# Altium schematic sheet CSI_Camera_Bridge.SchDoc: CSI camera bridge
size A3; Project: STM32MP15x-EVAL; Date: Not used; ApprovedBy: Not used; CheckedBy: Not used; Author: Not used; CompanyName: STMicroelectronics; DrawnBy: Not used; Engineer: Not used; Organization: Not used; Address1: Not used; Address2: Not used; Address3: Not used; Address4: Not used; DocumentNumber: 11; Revision: Not used; SheetNumber: 11; SheetTotal: 17
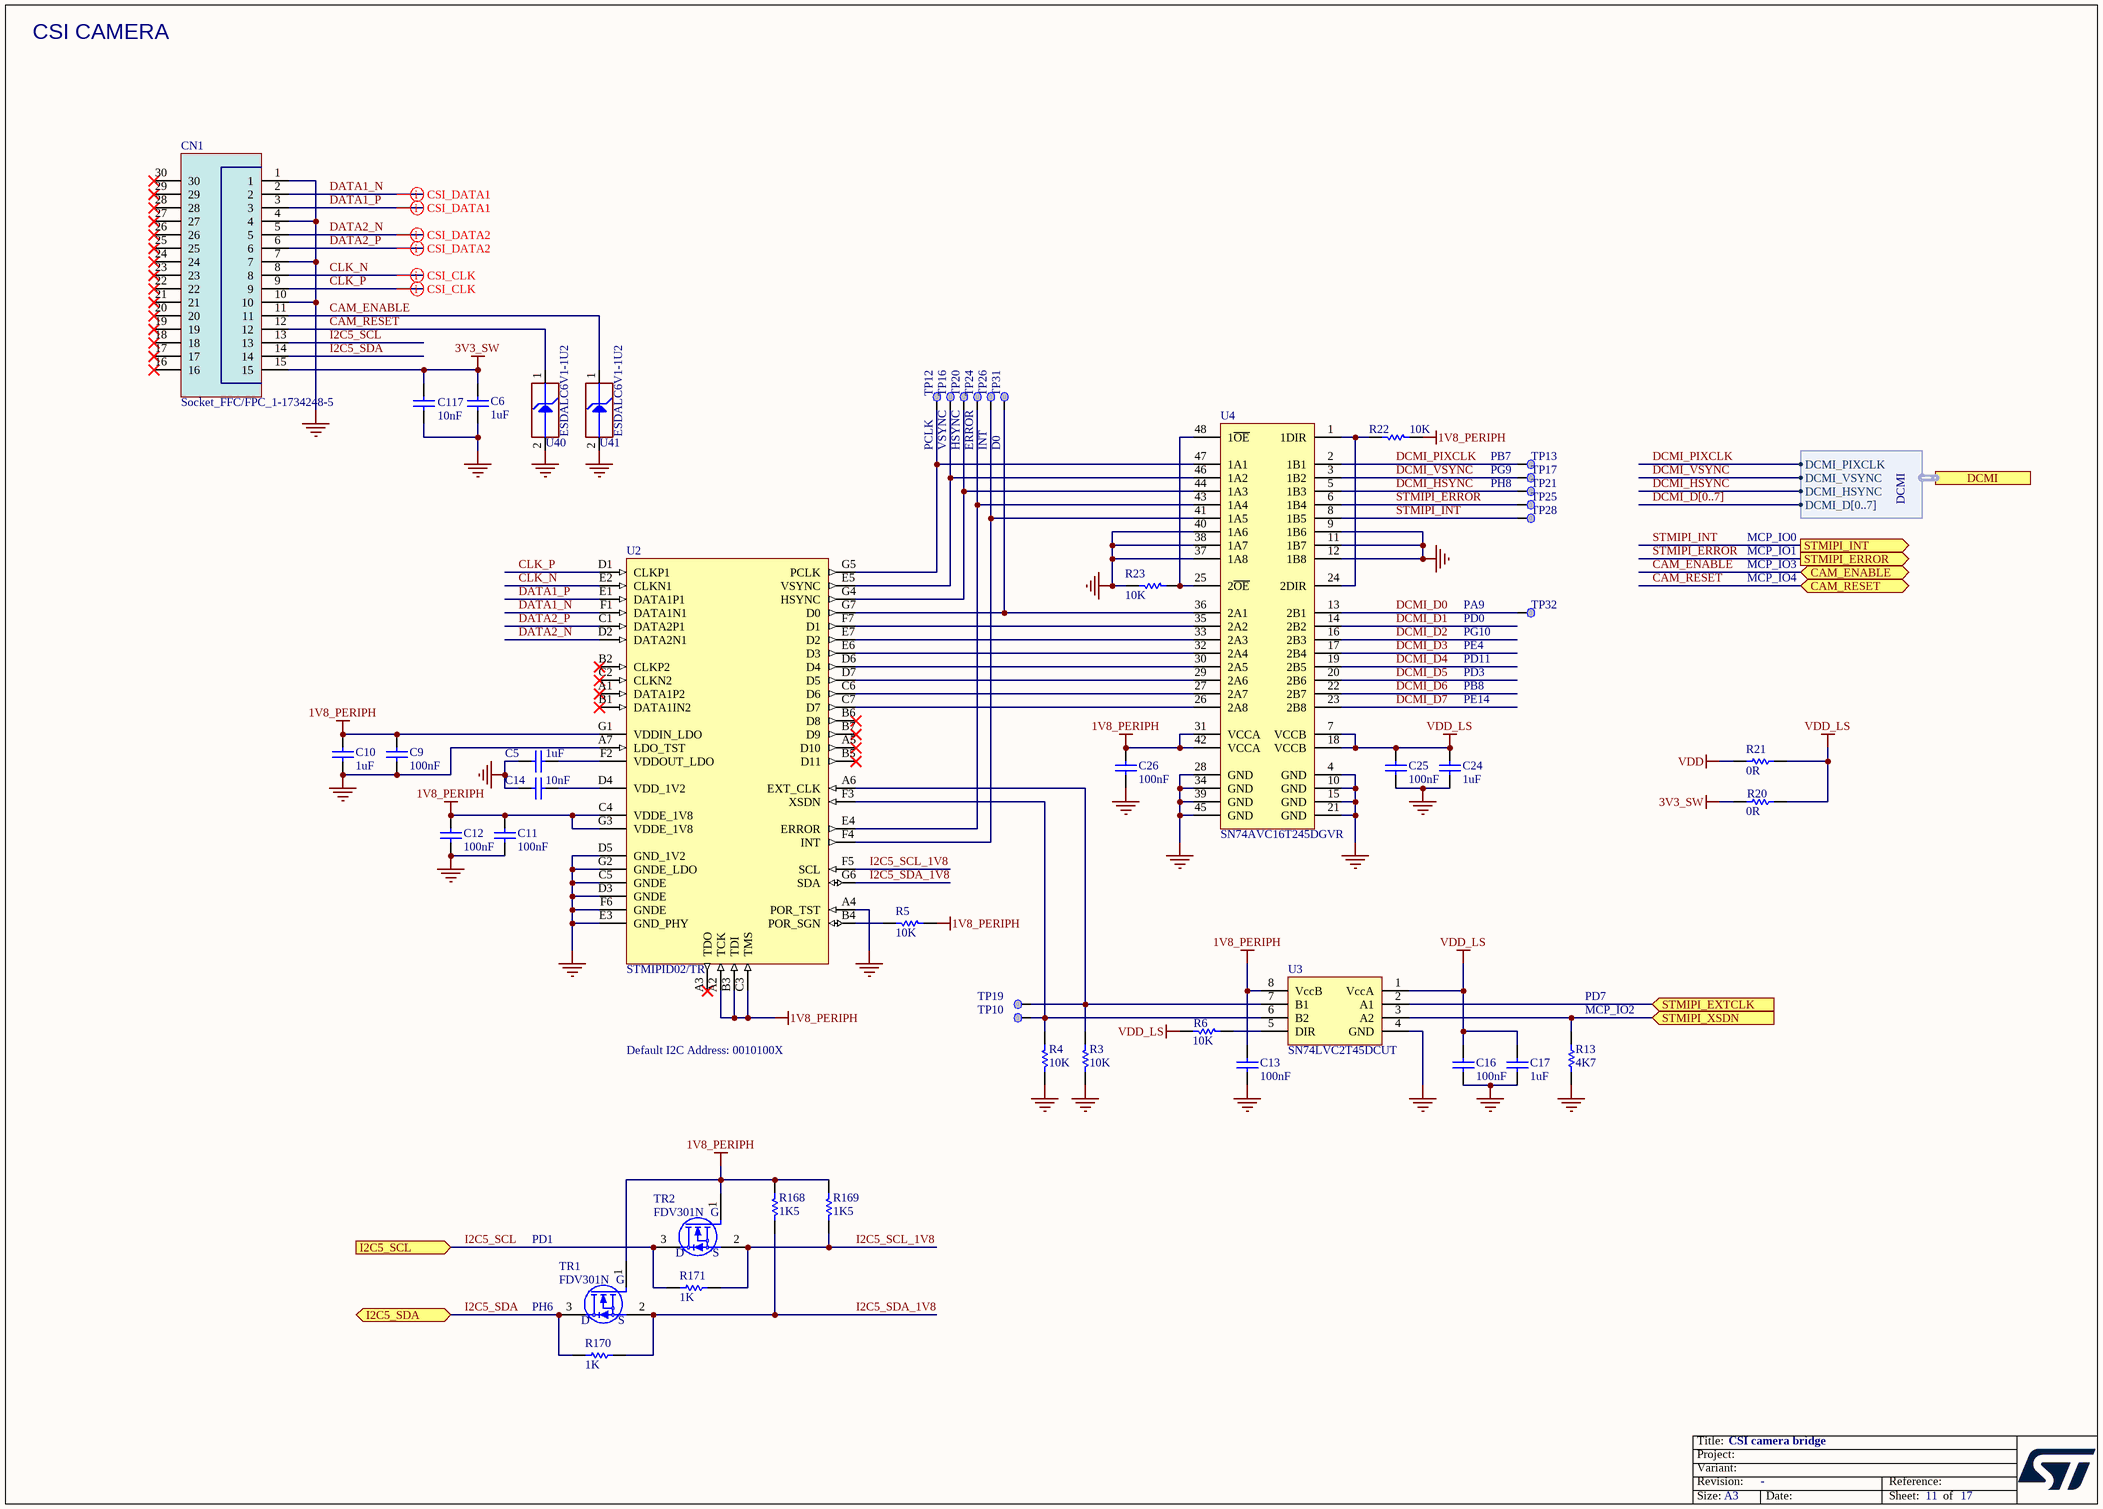
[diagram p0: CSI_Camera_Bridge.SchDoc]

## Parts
C5  value 1uF  [C0201_MURATA_GRM033_H0P3]  (hidden comment: Capacitor)
C6  value 1uF  [C0402]  (hidden comment: Capacitor)
C9  value 100nF  [C0402]  (hidden comment: Capacitor)
C10  value 1uF  [C0201_MURATA_GRM033_H0P3]  (hidden comment: Capacitor)
C11  value 100nF  [C0402]  (hidden comment: Capacitor)
C12  value 100nF  [C0402]  (hidden comment: Capacitor)
C13  value 100nF  [C0402]  (hidden comment: Capacitor)
C14  value 10nF  [C0402]  (hidden comment: Capacitor)
C16  value 100nF  [C0402]  (hidden comment: Capacitor)
C17  value 1uF  [C0201_MURATA_GRM033_H0P3]  (hidden comment: Capacitor)
C24  value 1uF  [C0201_MURATA_GRM033_H0P3]  (hidden comment: Capacitor)
C25  value 100nF  [C0402]  (hidden comment: Capacitor)
C26  value 100nF  [C0402]  (hidden comment: Capacitor)
C117  value 10nF  [C0402]  (hidden comment: Capacitor)
CN1  Socket_FFC/FPC_1-1734248-5  [CON_TE-CONNECTIVITY_1-1734248-5]
R3  value 10K  [R0402]  (hidden comment: Resistor)
R4  value 10K  [R0402]  (hidden comment: Resistor)
R5  value 10K  [R0402]  (hidden comment: Resistor)
R6  value 10K  [R0402]  (hidden comment: Resistor)
R13  value 4K7  [R0402]  (hidden comment: Resistor)
R20  value 0R  [R0402]  (hidden comment: Resistor)
R21  value 0R  [R0402]  (hidden comment: Resistor)
R22  value 10K  [R0402]  (hidden comment: Resistor)
R23  value 10K  [R0402]  (hidden comment: Resistor)
R168  value 1K5  [R0402]  (hidden comment: Resistor)
R169  value 1K5  [R0402]  (hidden comment: Resistor)
R170  value 1K  [R0402]  (hidden comment: Resistor)
R171  value 1K  [R0402]  (hidden comment: Resistor)
TP10  Test Point  [TP_SMD_1MM]  (value not drawn)  (no BOM)
TP12  Test Point  [TP_SMD_1MM]  (value not drawn)  (no BOM)
TP13  Test Point  [TP_SMD_1MM]  (value not drawn)  (no BOM)
TP16  Test Point  [TP_SMD_1MM]  (value not drawn)  (no BOM)
TP17  Test Point  [TP_SMD_1MM]  (value not drawn)  (no BOM)
TP19  Test Point  [TP_SMD_1MM]  (value not drawn)  (no BOM)
TP20  Test Point  [TP_SMD_1MM]  (value not drawn)  (no BOM)
TP21  Test Point  [TP_SMD_1MM]  (value not drawn)  (no BOM)
TP24  Test Point  [TP_SMD_1MM]  (value not drawn)  (no BOM)
TP25  Test Point  [TP_SMD_1MM]  (value not drawn)  (no BOM)
TP26  Test Point  [TP_SMD_1MM]  (value not drawn)  (no BOM)
TP28  Test Point  [TP_SMD_1MM]  (value not drawn)  (no BOM)
TP31  Test Point  [TP_SMD_1MM]  (value not drawn)  (no BOM)
TP32  Test Point  [TP_SMD_1MM]  (value not drawn)  (no BOM)
TR1  value FDV301N  [MOS_SOT23]  (hidden comment: BSN20)
TR2  value FDV301N  [MOS_SOT23]  (hidden comment: BSN20)
U2  value STMIPID02/TR  [ICC_VFBGA49_3X3_P040]  (hidden comment: STMIPID02)
U3  SN74LVC2T45DCUT  [ICC_VSSOP8_DCU_R-PDSO-G8_2X2P30_P050]
U4  SN74AVC16T245DGVR  [ICC_TVSOP48_9P8X6P6_P040]
U40  value ESDALC6V1-1U2  [ESD_ST0201]  (hidden comment: ESD-TRANSIL)
U41  value ESDALC6V1-1U2  [ESD_ST0201]  (hidden comment: ESD-TRANSIL)

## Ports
CAM_ENABLE (bidir), CAM_RESET (bidir), DCMI (harness DCMI), I2C5_SCL (in), I2C5_SDA (bidir), STMIPI_ERROR (out), STMIPI_EXTCLK (in), STMIPI_INT (out), STMIPI_XSDN (in)

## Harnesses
DCMI: DCMI_D[0..7], DCMI_HSYNC, DCMI_VSYNC, DCMI_PIXCLK

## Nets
1V8_PERIPH: C9.2 C10.2 C11.2 C12.2 C13.2 C26.2 R5.1 R22.2 R168.2 R169.2 TR1.1(G) TR2.1(G) U2.A2(TCK) U2.B3(TDI) U2.C3(TMS) U2.C4(VDDE_1V8) U2.G1(VDDIN_LDO) U2.G3(VDDE_1V8) U3.8(VccB) U4.31(VCCA) U4.42(VCCA)
3V3_SW: C6.2 C117.2 CN1.15 R20.2
GND: C5.1 C6.1 C9.1 C10.1 C11.1 C12.1 C13.1 C14.1 C16.1 C17.1 C24.1 C25.1 C26.1 C117.1 CN1.1 CN1.4 CN1.7 CN1.10 R3.2 R4.2 R13.1 R23.2 U2.A4(POR_TST) U2.A7(LDO_TST) U2.C5(GNDE) U2.D3(GNDE) U2.D5(GND_1V2) U2.E3(GND_PHY) U2.F6(GNDE) U2.G2(GNDE_LDO) U3.4(GND) U4.4(GND) U4.9(1B6) U4.10(GND) U4.11(1B7) U4.12(1B8) U4.15(GND) U4.21(GND) U4.28(GND) U4.34(GND) U4.37(1A8) U4.38(1A7) U4.39(GND) U4.40(1A6) U4.45(GND) U40.2(GND) U41.2(GND)
VDD: R21.2
VDD_LS: C16.2 C17.2 C24.2 C25.2 R6.2 R20.1 R21.1 U3.1(VccA) U4.7(VCCB) U4.18(VCCB)
CAM_ENABLE: CN1.11 U41.1(IO1) ; port CAM_ENABLE
CAM_RESET: CN1.12 U40.1(IO1) ; port CAM_RESET
CLK_N: CN1.8 U2.E2(CLKN1)
CLK_P: CN1.9 U2.D1(CLKP1)
DATA1_N: CN1.2 U2.F1(DATA1N1)
DATA1_P: CN1.3 U2.E1(DATA1P1)
DATA2_N: CN1.5 U2.D2(DATA2N1)
DATA2_P: CN1.6 U2.C1(DATA2P1)
DCMI_D0: TP32.1 U4.13(2B1)
DCMI_D1: U4.14(2B2)
DCMI_D2: U4.16(2B3)
DCMI_D3: U4.17(2B4)
DCMI_D4: U4.19(2B5)
DCMI_D5: U4.20(2B6)
DCMI_D6: U4.22(2B7)
DCMI_D7: U4.23(2B8)
DCMI_HSYNC: TP21.1 U4.5(1B3) ; port DCMI.DCMI_HSYNC
DCMI_PIXCLK: TP13.1 U4.2(1B1) ; port DCMI.DCMI_PIXCLK
DCMI_VSYNC: TP17.1 U4.3(1B2) ; port DCMI.DCMI_VSYNC
I2C5_SCL: CN1.13 R171.2 TR2.3(D) ; port I2C5_SCL
I2C5_SCL_1V8: R169.1 R171.1 TR2.2(S) U2.F5(SCL)
I2C5_SDA: CN1.14 R170.2 TR1.3(D) ; port I2C5_SDA
I2C5_SDA_1V8: R168.1 R170.1 TR1.2(S) U2.G6(SDA)
STMIPI_ERROR: TP25.1 U4.6(1B4) ; port STMIPI_ERROR
STMIPI_EXTCLK: U3.2(A1) ; port STMIPI_EXTCLK
STMIPI_INT: TP28.1 U4.8(1B5) ; port STMIPI_INT
STMIPI_XSDN: R13.2 U3.3(A2) ; port STMIPI_XSDN
NetC5_2: C5.2 U2.F2(VDDOUT_LDO)
NetC14_2: C14.2 U2.D4(VDD_1V2)
NetR3_1: R3.1 TP19.1 U2.A6(EXT_CLK) U3.7(B1)
NetR4_1: R4.1 TP10.1 U2.F3(XSDN) U3.6(B2)
NetR5_2: R5.2 U2.B4(POR_SGN)
NetR6_1: R6.1 U3.5(DIR)
NetR22_1: R22.1 U4.1(1DIR) U4.24(2DIR)
NetR23_1: R23.1 U4.25(2~{OE}) U4.48(1~{OE})
NetTP12_1: TP12.1 U2.G5(PCLK) U4.47(1A1)
NetTP16_1: TP16.1 U2.E5(VSYNC) U4.46(1A2)
NetTP20_1: TP20.1 U2.G4(HSYNC) U4.44(1A3)
NetTP24_1: TP24.1 U2.E4(ERROR) U4.43(1A4)
NetTP26_1: TP26.1 U2.F4(INT) U4.41(1A5)
NetTP31_1: TP31.1 U2.G7(D0) U4.36(2A1)
NetU2_C6: U2.C6(D6) U4.27(2A7)
NetU2_C7: U2.C7(D7) U4.26(2A8)
NetU2_D6: U2.D6(D4) U4.30(2A5)
NetU2_D7: U2.D7(D5) U4.29(2A6)
NetU2_E6: U2.E6(D3) U4.32(2A4)
NetU2_E7: U2.E7(D2) U4.33(2A3)
NetU2_F7: U2.F7(D1) U4.35(2A2)

Not connected (* = marked no-connect by the designer): CN1 16* 17* 18* 19* 20* 21* 22* 23* 24* 25* 26* 27* 28* 29* 30*; U2 A1(DATA1P2)* A3(TDO)* A5(D10)* B1(DATA1IN2)* B2(CLKP2)* B5(D11)* B6(D8)* B7(D9)* C2(CLKN2)*

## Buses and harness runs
bus DCMI_D[0..7]

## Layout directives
differential pair: CLK_N, CLK_P, DATA1_N, DATA1_P, DATA2_N, DATA2_P

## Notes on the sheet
- CSI CAMERA
- PCLK
- VSYNC
- HSYNC
- ERROR
- INT
- D0
- PH8
- PG9
- PB7
- MCP_IO1
- MCP_IO0
- MCP_IO4
- MCP_IO3
- (near TP32) PA9
- (near TP32) PD0
- (near TP32) PG10
- PE4
- PD11
- PD3
- PB8
- PE14
- Default I2C Address: 0010100X
- (near R13) PD7
- (near R13) MCP_IO2
- PD1
- PH6

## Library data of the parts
C5 C10 C17 C24 = MCD-02377: Capacitor, MLCC, 1uF, 6.3V, X5R, +/-20%, 0201, T=0,3mm; Manufacturer_Part_Number: GRM033R60J105MEA2; Manufacturer: MURATA; Part_Preference: Recommended; Partial_Alternate_Internal_Part_Number: MCD-04356; Order_Code_RS: 820-0643; Component_Country_Of_Origin: Japan°; ShowFields: YES; ID: 4483
C6 = MCD-00095: Capacitor, MLCC, 1uF, 25V, X5R, +/-10%, 0402, T=0.5mm; Manufacturer_Part_Number: GRM155R61E105KA12; Manufacturer: MURATA; Part_Preference: Recommended; Partial_Alternate_Internal_Part_Number: MCD-04188; Order_Code_RS: 2218855; Component_Country_Of_Origin: Japan°°; ShowFields: YES; ID: 2772
C9 C11-C13 C16 C25 C26 = MCD-00006: Capacitor, MLCC, 100nF, 16V, X7R, +/-10%, 0402, T=0.5mm; Manufacturer_Part_Number: CC0402KRX7R7BB104; Manufacturer: YAGEO; Part_Preference: Recommended; Partial_Alternate_Internal_Part_Number: MCD-03299; Order_Code_RS: 9402047; Component_Country_Of_Origin: China; ShowFields: YES; ID: 2474
C14 = MCD-02198: Capacitor, MLCC, 10nF, 50V, X7R, +/-10%, 0402, T=0.5mm; Manufacturer_Part_Number: CC0402KRX7R9BB103; Manufacturer: YAGEO; Part_Preference: Recommended; Order_Code_RS: 6169644; Component_Country_Of_Origin: China; ShowFields: YES; ID: 4298
C117 = MCD-02198: Capacitor, MLCC, 10nF, 50V, X7R, +/-10%, 0402, T=0.5mm; Part_Preference: Recommended; Manufacturer: YAGEO; Manufacturer_Part_Number: CC0402KRX7R9BB103; Order_Code_RS: 6169644; Component_Country_Of_Origin: China; ShowFields: YES; ID: 4298
CN1 = MCD-02225: Socket_FFC/FPC, 15pins, 1mm ,VR, SMD, T=7.7mm; Part_Preference: Recommended; Part_Type: Connector; Manufacturer: TE CONNECTIVITY; Component_Country_Of_Origin: Taiwan; ShowFields: YES; ID: 4325
R3 R4 R6 R22 R23 = MCD-00053: Resistor, 10K, 0402, +/-1%, 1/16W; Part_Preference: Recommended; Manufacturer: YAGEO; Manufacturer_Part_Number: RC0402FR-0710KL; BMS_Part_Number: 9131590; Order_Code_RS: 9239359; Component_Country_Of_Origin: China; ShowFields: YES; ID: 2539
R5 = MCD-00053: Resistor, 10K, 0402, +/-1%, 1/16W; BMS_Part_Number: 9131590; Part_Preference: Recommended; Manufacturer: YAGEO; Manufacturer_Part_Number: RC0402FR-0710KL; Order_Code_RS: 9239359; Component_Country_Of_Origin: China; ShowFields: YES; ID: 2539
R13 = MCD-00065: Resistor, 4K7, 0402, +/-1%, 1/16W; Manufacturer_Part_Number: RC0402FR-074K7L; Manufacturer: YAGEO; Part_Preference: Recommended; Partial_Alternate_Internal_Part_Number: MCD-03300; Order_Code_RS: 9239316; Component_Country_Of_Origin: China; ShowFields: YES; ID: 2526
R20 R21 = MCD-00052: Resistor, 0R, 0402, +/-5%, 1/16W; Part_Preference: Recommended; Manufacturer: YAGEO; Manufacturer_Part_Number: RC0402JR-070RL; Order_Code_RS: 9232516RL; Component_Country_Of_Origin: China; ShowFields: YES; ID: 2540
R168 R169 = MCD-00068: Resistor, 1K5, 0402, +/-1%, 1/16W; Part_Preference: Recommended; Manufacturer: YAGEO; Manufacturer_Part_Number: RC0402FR-071K5L; Order_Code_RS: 9239251; Component_Country_Of_Origin: China; ShowFields: YES; ID: 2524
R170 R171 = MCD-00061: Resistor, 1K, 0402, +/-1%,1/16W; Part_Preference: Recommended; Manufacturer: YAGEO; Manufacturer_Part_Number: RC0402FR-071KL; Order_Code_RS: 9239235; Component_Country_Of_Origin: China; ShowFields: YES; ID: 2532
TP10 TP12 TP13 TP16 TP17 TP19-TP21 TP24-TP26 TP28 TP31 TP32 = MCD-00074: Test Point 1mm; Part_Type: Misc; Part_Preference: Recommended; ShowFields: YES; ID: 2518; Component_Country_Of_Origin: Unknown
TR1 TR2 = MCD-02156: MOSFET, N-Channel , Vds: 25V, Id: 0,22A, Vgs(th): 1.06V, Vgs(max): +/-8V, Rdson:5ohm@Vgs=2.7V, Qg=0,49nC; Part_Preference: Recommended; Part_Type: Transistor; Manufacturer: ON SEMICONDUCTOR; Component_Country_Of_Origin: China°°; ShowFields: YES; ID: 4256
U2 = MCD-02213: Dual mode MIPI CSI-2 / SMIA CCP2 de-serializer; Part_Preference: Forbidden; Part_Type: IC; Manufacturer: STMICROELECTRONICS; Manufacturer_HQ_COO: EU; Component_Country_Of_Origin: Malaysia; ShowFields: YES; ID: 4313
U3 = MCD-00264: Dual bit dual supply bus transceiver; BMS_Part_Number: 9169311; Part_Preference: Recommended; Part_Type: IC; Manufacturer: TEXAS INSTRUMENTS; Component_Country_Of_Origin: Thailand; ShowFields: YES; ID: 2605; Order_Code_RS: 922-2870
U4 = MCD-02226: 16-bit translating transceiver; Part_Preference: Recommended; Part_Type: IC; Manufacturer: TEXAS INSTRUMENTS; Component_Country_Of_Origin: Malaysia; ShowFields: YES; ID: 4326
U40 U41 = MCD-00170: ESD protection 6V1; BMS_Part_Number: 9151132; Part_Type: Diode; Part_Preference: Recommended; Manufacturer: STMICROELECTRONICS; Manufacturer_HQ_COO: EU; Component_Country_Of_Origin: China; ShowFields: YES; ID: 2696; Order_Code_RS: 795-8404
